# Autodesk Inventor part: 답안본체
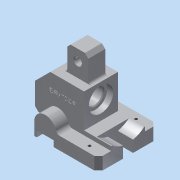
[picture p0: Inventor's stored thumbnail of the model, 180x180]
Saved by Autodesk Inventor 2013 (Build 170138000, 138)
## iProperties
Created: 2016-11
Part Number: 답안본체
Material: 알루미늄 6061
Document SubType Name: Modeling
Designer: Administrator
Density: 2.71 g/cm^3
Mass: 472.773 g
Surface Area: 322.301 cm^2
Volume: 174.455 cm^3
Author: Administrator
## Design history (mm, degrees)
sketch "스케치2"
  geometry: L1 (-38, 35)-(38, 35); L2 (38, 35)-(38, -35); L3 (38, -35)-(-38, -35); L4 (-38, -35)-(-38, 35); L5 (-38, 35)-(38, -35); L6 (38, 35)-(-38, -35); 1 further point
  constraints: 12 end point, 2 midpoint, 2 parallel, 1 horizontal, 1 perpendicular
  dimensions: "d0" = 76 distance of L2.end L3.end; "d1" = 70 distance of L1.end L2.end
extrude "돌출1" new body sketch "스케치2" distance "d2" = 15; taper "d3" = 0 deg
sketch "스케치5"
  geometry: C1 r 13 at (13, 15); 2 further points
  constraints: 1 centre point, 1 horizontal alignment
  dimensions: "d11" = 26 diameter of C1; "d13" = 13 distance of C1.centre point (0, 15)
extrude "돌출3" join sketch "스케치5" stored distance "d14" = 15; taper "d15" = 0 deg
sketch "스케치3"
  geometry: L1 (3, 7)-(23, 7); L2 (23, 7)-(23, 0); L3 (23, 0)-(3, 0); L4 (3, 0)-(3, 7); L5 (0, 0)-(0, 15) reference; 1 further point
  constraints: 8 end point, 2 parallel, 1 horizontal, 1 horizontal alignment, 1 perpendicular
  dimensions: "d4" = 20 distance of L2.end L3.end; "d5" = 7 distance of L1.end L2.end; "d6" = 3 distance between parallel lines of L4 L5
extrude "돌출2" cut sketch "스케치3" stored distance "d7" = 15; taper "d8" = 0 deg
fillet "모깎기1" dims "d16" = 5
sketch "스케치6"
  geometry: L1 (-38, 15)-(7.708, 15) reference; L2 (-38, 0)-(-38, 15) reference; L3 (35, 7)-(15, 7) reference; L4 (15, 7)-(15, 0) reference; L5 (15, 0)-(-38, 0) reference; L6 (-38, 0)-(-38, 15) reference; L7 (-38, 15)-(7.708, 15) reference; L8 (38, 15)-(38, 0) reference; L9 (38, 0)-(35, 0) reference; L10 (35, 0)-(35, 7) reference; L11 (34, 60)-(-6, 60); L12 (-6, 60)-(-6, 20); L13 (-6, 20)-(-38, 20); L14 (52, 42)-(52, 16); L15 (48, 12)-(-38, 12); L16 (-38, 12)-(-38, 20); L17 (34, 60)-(52, 42); L18 (52, 16)-(48, 12); A1 r 5 centre (7.708, 20) between (7.708, 15) and (12.512, 18.611) reference; A2 r 13 centre (25, 15) between (38, 15) and (12.512, 18.611) reference; 3 further points
  constraints: 16 end point, 5 point on line, 4 perpendicular
  dimensions: "d85" = 60 distance between parallel lines of L5 L11; "d89" = 58 distance of point (52, 60) L11.end; "d90" = 48 distance of point (52, 60) point (52, 12); "d91" = 18 distance of L11.start point (52, 60); "d92" = 18 distance of L14.start point (52, 60) (= d91); "d93" = 4 distance of L14.end point (52, 12); "d94" = 4 distance of L15.start point (52, 12) (= d93); "d95" = 48 distance between parallel lines of L15 L11
extrude "돌출4" join sketch "스케치6" stored distance "d26" = 40; taper "d27" = 0 deg
hole "구멍1" diameter "d30" = 20; stored, may be unused: countersink angle "d34" = 90 deg, drill point angle "d36" = 118 deg; dims "d28" = 42, "d29" = 20, "d31" = 6, "d32" = 29, "d33" = 7, "d35" = 8
chamfer "모따기1" distance "d37" = 1; stored, may be unused: second distance "d38" = 2, angle "d39" = 45 deg
sketch "스케치7"
  geometry: L1 (2, 52)-(1, 53) reference; L2 (1, 53)-(1, 56.5) reference; L3 (1, 56.5)-(-6, 56.5) reference; L4 (-6, 56.5)-(-6, 60) reference; L5 (-6, 60)-(34, 60) reference; L6 (42, 52)-(2, 52) reference; L7 (35, 7)-(15, 7) reference; L8 (15, 7)-(15, 0) reference; L9 (15, 0)-(-38, 0) reference; L10 (-38, 0)-(-38, 20) reference; L11 (-38, 20)-(-6, 20) reference; L12 (-6, 20)-(-6, 27.5) reference; L13 (-6, 27.5)-(1, 27.5) reference; L14 (1, 27.5)-(1, 31) reference; L15 (1, 31)-(2, 32) reference; L16 (2, 32)-(52, 32) reference; L17 (38, 12)-(38, 0) reference; L18 (38, 0)-(35, 0) reference; L19 (35, 0)-(35, 7) reference; L20 (-1, 60)-(-1, 86); L21 (3, 90)-(20, 90); L22 (24, 86)-(24, 60); L23 (20, 90)-(24, 86); L24 (3, 90)-(-1, 86); L25 (34, 60)-(42, 52) reference; L26 (52, 32)-(52, 16) reference; L27 (52, 16)-(48, 12) reference; L28 (48, 12)-(38, 12) reference; 3 further points
  constraints: 10 end point, 6 point on line, 2 perpendicular, 1 parallel
  dimensions: "d40" = 5 distance between parallel lines of L4 L20; "d41" = 25 distance between parallel lines of L20 L22; "d42" = 90 distance between parallel lines of L9 L21; "d43" = 4 distance of L21.end point (24, 90); "d44" = 4 distance of L22.start point (24, 90) (= d43); "d45" = 4 distance of L21.start point (-1, 90) (= d43); "d46" = 4 distance of L20.end point (-1, 90) (= d45)
extrude "돌출5" join sketch "스케치7" stored distance "d47" = 20; taper "d48" = 0 deg
fillet "모깎기2" dims "d49" = 3
hole "구멍2" diameter "d52" = 8; stored, may be unused: countersink angle "d56" = 90 deg, drill point angle "d58" = 118 deg; dims "d50" = 77, "d51" = 12.5, "d53" = 6, "d54" = 29, "d55" = 7, "d57" = 8
chamfer "모따기2" distance "d59" = 1; stored, may be unused: second distance "d60" = 2, angle "d61" = 45 deg
chamfer "모따기3" distance "d62" = 5; stored, may be unused: second distance "d63" = 2, angle "d64" = 45 deg
hole "구멍3" diameter "d67" = 3.242; stored, may be unused: countersink angle "d71" = 90 deg, drill point angle "d73" = 118 deg; dims "d65" = 18, "d66" = 7.5, "d68" = 18, "d69" = 29, "d70" = 7, "d72" = 8
node "작업 평면1"
sketch "스케치9"
  geometry: L1 (20, 50)-(20, -10) reference; L2 (20, 14)-(0, 14); L3 (0, 14)-(0, 26); L4 (0, 26)-(20, 26); L5 (20, 26)-(20, 14); C1 r 29 at (-22, 20); 3 further points
  constraints: 8 end point, 3 midpoint, 2 parallel, 1 centre point, 1 horizontal, 1 horizontal alignment, 1 perpendicular
  dimensions: "d79" = 58 diameter of C1; "d80" = 42 distance of point (20, 20) C1.centre; "d81" = 20 distance of L3.end L4.end; "d82" = 12 distance of L2.end L3.end
extrude "돌출6" cut sketch "스케치9" distance "d83" = 18; taper "d84" = 0 deg
sketch "스케치8"
  geometry: L1 (6, 20)-(6, 60) reference; 4 further points; 1 other entity
  constraints: 2 other
  dimensions: "d75" = 18 dimension on point (-19, 42); "d76" = 25 distance from line of point (-19, 42) L1
feature "엠보싱1" sketch "스케치8" dims "d77" = 0.5, "d78" = 0
node "솔리드1"
mirror "대칭1"
node "절단 모서리 투영1"
node "절단 모서리 투영2"
